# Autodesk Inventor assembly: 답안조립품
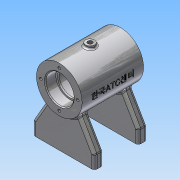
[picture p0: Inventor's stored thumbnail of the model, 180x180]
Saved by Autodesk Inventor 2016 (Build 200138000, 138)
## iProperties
Created: 2018-05
Part Number: 답안조립품
Material: 일반
Document SubType Name: Assembly
Designer: Administrator
Author: Administrator
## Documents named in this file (2)
- C:\Users\Administrator\Desktop\480507V1017\답안조립품.iam
- C:\Users\Administrator\Desktop\480507V1017\본체.ipt
